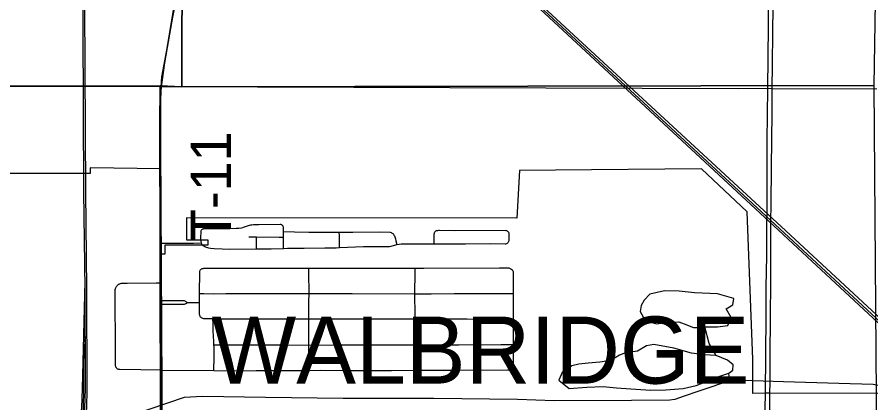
# Model space of a CAD drawing. Extents: x 0 to 40.2, y 0 to 22.
# Drawn here: x 4.538 to 5.744, y 15.808 to 16.354 of the extents above; entities that cross this region are included whole.
import ezdxf

# ---------------------------------------------------------------- set-up
doc = ezdxf.new("R2010")
doc.units = 0
for name, color, linetype in [('GM_X_Corporation', 7, 'Continuous'), ('GM_X_County_Road_Text', 7, 'Continuous'), ('GM_X_Major_River', 7, 'Continuous'), ('GM_X_Minor_Lake', 7, 'Continuous'), ('GM_X_Minor_Lake_Text', 7, 'Continuous'), ('GM_X_Rail_Line', 7, 'Continuous'), ('GM_X_Unincorporated', 7, 'Continuous'), ('GM_X_Unincorporated_Location', 7, 'Continuous'), ('GM_X_US_Location', 7, 'Continuous')]:
    doc.layers.add(name, color=color, linetype=linetype)

msp = doc.modelspace()

# ---------------------------------------------------------------- linework, layer by layer
at = {"layer": 'GM_X_Corporation'}
for points in [[(4.773, 17.2675), (4.7705, 16.2552), (4.7398, 16.2563), (3.7748, 16.2549), (3.7642, 17.2609)], [(4.773, 17.2675), (5.7644, 17.2596), (5.7484, 16.2569), (4.7705, 16.2552)], [(3.7748, 16.2549), (4.7398, 16.2563), (4.745, 15.3208), (3.7481, 15.3357), (3.7456, 16.2537)], [(5.7484, 16.2569), (5.7558, 15.3168), (4.745, 15.3208), (4.7398, 16.2563), (4.7705, 16.2552)]]:
    msp.add_lwpolyline(points, close=True, dxfattribs=at)
for points in [[(2.952, 16.2558), (3.7668, 16.256), (3.978, 16.2564), (4.3662, 15.7222), (4.3657, 15.832), (4.4899, 15.8293), (4.4389, 16.1327), (4.4182, 16.2558), (4.7417, 16.2555), (5.5568, 16.2525), (5.5984, 16.253), (5.6048, 16.2528), (5.7527, 16.2521)], [(5.7542, 15.8217), (5.6015, 15.8223), (5.5951, 15.8223), (5.5775, 15.8216), (5.5774, 15.8697), (5.5697, 16.0785), (5.5049, 16.1393), (5.3497, 16.1377), (5.2476, 16.1366), (5.2442, 16.0695), (4.777, 16.0697), (4.777, 16.039), (4.8072, 16.039), (4.8072, 16.0311), (4.7465, 16.0314), (4.7465, 16.0187), (4.741, 16.0186), (4.741, 16.0345), (4.7408, 16.1389), (4.6409, 16.1407), (4.641, 16.1323), (4.4389, 16.1327)]]:
    msp.add_lwpolyline(points, dxfattribs=at)
at = {"layer": 'GM_X_Major_River'}
for points in [[(4.1455, 17.415), (4.1542, 17.4069), (4.3224, 17.2484), (4.5126, 17.0764), (4.6277, 16.9694), (4.7733, 16.8366), (5.084, 16.5474), (5.609, 16.0605), (6.0377, 15.6628), (6.1678, 15.5423), (6.5654, 15.1729), (7.036, 14.7358), (7.4144, 14.3845), (7.7209, 14.1)], [(4.1471, 17.4167), (4.1558, 17.4086), (4.3239, 17.2501), (4.5142, 17.0781), (4.6293, 16.9711), (4.7748, 16.8383), (5.0856, 16.5491), (5.6113, 16.0632), (6.0399, 15.6663), (6.1698, 15.5443), (6.5669, 15.1758), (7.0383, 14.7375), (7.4155, 14.3872), (7.7237, 14.1)], [(4.595, 15.7016), (4.5966, 15.7037), (4.6105, 15.7227), (4.6181, 15.7396), (4.6243, 15.7572), (4.6309, 15.7811), (4.6337, 15.8009), (4.6346, 15.8282), (4.6339, 15.9696), (4.6323, 16.1067), (4.6306, 16.4569), (4.6254, 16.8469), (4.6254, 16.9694), (4.6218, 17.3067), (4.6212, 17.3587), (4.6206, 17.424)], [(4.5969, 15.7002), (4.5984, 15.7023), (4.6125, 15.7215), (4.6203, 15.7387), (4.6265, 15.7565), (4.6332, 15.7806), (4.6361, 15.8007), (4.637, 15.8282), (4.6362, 15.9697), (4.6347, 16.1067), (4.633, 16.4569), (4.6278, 16.847), (4.6277, 16.9694), (4.6241, 17.3067), (4.6236, 17.3587), (4.623, 17.424)], [(4.7243, 16.8813), (4.7752, 16.8317), (5.0824, 16.5458), (5.6074, 16.0588), (6.0352, 15.6606), (6.1639, 15.542), (6.5637, 15.1714), (7.0334, 14.7344), (7.4114, 14.3836), (7.7174, 14.1)], [(4.773, 16.8372), (4.7746, 16.4892), (4.7716, 16.4434), (4.7496, 16.309), (4.7417, 16.2693), (4.7392, 16.2247), (4.7399, 15.7814), (4.7434, 15.1836)], [(4.5912, 15.7043), (4.5928, 15.7065), (4.6065, 15.725), (4.6138, 15.7413), (4.6198, 15.7586), (4.6264, 15.7821), (4.6291, 15.8013), (4.63, 15.8283), (4.6338, 15.9798)], [(4.5931, 15.703), (4.5947, 15.7051), (4.6085, 15.7238), (4.6159, 15.7405), (4.622, 15.7579), (4.6286, 15.7816), (4.6314, 15.8011), (4.6323, 15.8282), (4.6321, 15.8675), (4.6343, 15.9023)]]:
    msp.add_lwpolyline(points, dxfattribs=at)
at = {"layer": 'GM_X_Minor_Lake'}
for points in [[(5.5258, 15.8755), (5.516, 15.8925), (5.5098, 15.9158)], [(5.5489, 15.8408), (5.6211, 15.8385), (5.699, 15.8364), (5.7478, 15.8349), (5.7802, 15.8283), (5.8134, 15.8228), (5.8409, 15.8225), (5.8804, 15.8707), (5.9029, 15.8722), (5.9152, 15.8724), (5.9231, 15.8681), (5.9338, 15.8524), (5.9479, 15.8355), (5.9601, 15.8315), (5.9759, 15.8354), (5.9938, 15.8408)], [(5.5489, 15.8408), (5.544, 15.8456), (5.5438, 15.8503)], [(5.5489, 15.8408), (5.4998, 15.8245), (5.4804, 15.818), (5.4675, 15.8132), (5.4603, 15.8122), (5.4062, 15.8116), (5.2968, 15.8114), (5.245, 15.813), (5.1266, 15.8146), (4.9988, 15.8147), (4.8887, 15.8158), (4.8002, 15.8172), (4.7741, 15.8161), (4.6767, 15.7828), (4.6101, 15.7576), (4.5602, 15.7399), (4.5188, 15.7284), (4.4621, 15.7046), (4.432, 15.6949), (4.4188, 15.6924), (4.4043, 15.6911), (4.3976, 15.6884)]]:
    msp.add_lwpolyline(points, dxfattribs=at)
at = {"layer": 'GM_X_Minor_Lake_Text'}
for p, q in [((5.5015, 15.9151), (5.5098, 15.9158)), ((5.4547, 15.827), (5.479, 15.8287))]:
    msp.add_line(p, q, dxfattribs=at)
for points in [[(5.5098, 15.9158), (5.5276, 15.916), (5.5424, 15.9175), (5.547, 15.9288), (5.5399, 15.9414), (5.5494, 15.947), (5.5509, 15.9557), (5.5275, 15.9623), (5.495, 15.9637), (5.4735, 15.9661), (5.4527, 15.9666), (5.4322, 15.9622), (5.4238, 15.9535), (5.4196, 15.9459), (5.4184, 15.9376), (5.4255, 15.925), (5.4414, 15.92), (5.4577, 15.9226), (5.4728, 15.9228), (5.4803, 15.9201), (5.4939, 15.9147), (5.5015, 15.9151)], [(5.479, 15.8287), (5.4975, 15.8328), (5.5157, 15.8402), (5.5279, 15.8451), (5.5438, 15.8503), (5.5491, 15.8548), (5.5499, 15.862), (5.5416, 15.8689), (5.5258, 15.8755), (5.5088, 15.8763), (5.491, 15.8787), (5.4661, 15.8857), (5.4378, 15.8908), (5.4272, 15.889), (5.4146, 15.8815), (5.3976, 15.8789), (5.3893, 15.876), (5.3767, 15.8681), (5.3612, 15.8659), (5.3446, 15.8645), (5.3317, 15.8631), (5.3218, 15.8609), (5.3082, 15.8515), (5.3036, 15.8405), (5.3182, 15.8286), (5.3428, 15.8304), (5.3659, 15.8314), (5.3848, 15.8297), (5.4052, 15.8281), (5.4332, 15.8264), (5.4547, 15.827)]]:
    msp.add_lwpolyline(points, dxfattribs=at)
at = {"layer": 'GM_X_Rail_Line'}
msp.add_line((4.7412, 16.018), (4.7413, 16.034), dxfattribs=at)
for points in [[(4.7419, 16.255), (4.7436, 16.268), (4.7467, 16.2889), (4.7536, 16.3294), (4.7579, 16.3533), (4.7638, 16.3851), (4.7681, 16.4109), (4.7706, 16.4273), (4.7736, 16.4484), (4.7745, 16.4578), (4.7752, 16.4634), (4.7757, 16.4688), (4.776, 16.4747), (4.7763, 16.482), (4.7767, 16.4988), (4.7767, 16.508)], [(4.7409, 16.1384), (4.741, 16.1539), (4.7407, 16.1732), (4.7407, 16.2), (4.7407, 16.223), (4.741, 16.2361), (4.7415, 16.2491), (4.7419, 16.255)], [(4.7413, 16.034), (4.741, 16.1012), (4.7411, 16.1139), (4.7409, 16.1374), (4.7409, 16.1384)], [(4.7413, 16.034), (4.7514, 16.034), (4.7675, 16.0341), (4.7779, 16.0341), (4.7872, 16.0342), (4.7977, 16.0344)], [(4.7416, 15.9778), (4.7415, 15.9952), (4.7412, 16.0151), (4.7412, 16.018)], [(4.7417, 15.9478), (4.7416, 15.953), (4.7416, 15.9559), (4.7416, 15.9721), (4.7416, 15.9778)], [(4.742, 15.9054), (4.7418, 15.9205), (4.7419, 15.9329), (4.7417, 15.9478)], [(4.7422, 15.8545), (4.7422, 15.8974), (4.742, 15.9054)], [(4.7417, 15.7843), (4.7417, 15.8139), (4.7422, 15.8545)]]:
    msp.add_lwpolyline(points, dxfattribs=at)
at = {"layer": 'GM_X_Unincorporated'}
for points in [[(5.605, 16.2523), (5.6055, 16.2864), (5.6059, 16.3318), (5.6062, 16.3679), (5.6068, 16.4412), (5.6077, 16.5109), (5.6092, 16.6091), (5.6095, 16.6701), (5.6096, 16.6826), (5.6096, 16.7167), (5.6102, 16.7509), (5.6104, 16.7643), (5.6109, 16.7907), (5.6114, 16.8342), (5.6113, 16.8517)], [(5.5926, 15.6316), (5.594, 15.6823), (5.5945, 15.7165), (5.5947, 15.7625), (5.595, 15.8004), (5.5953, 15.8217), (5.5962, 15.9315), (5.5964, 15.9719), (5.5971, 16.016), (5.5975, 16.0546), (5.5977, 16.0869), (5.5977, 16.1485), (5.5979, 16.1789), (5.5986, 16.2524), (5.5995, 16.3412), (5.6, 16.3965)], [(5.6017, 15.8217), (5.6018, 15.8379), (5.6022, 15.8714), (5.6026, 15.9324), (5.6031, 15.9765), (5.6032, 16.0144), (5.6031, 16.0636), (5.6034, 16.0903), (5.6041, 16.1407), (5.6045, 16.1805), (5.6048, 16.2178), (5.605, 16.2523)], [(5.6017, 15.573), (5.6013, 15.6309), (5.601, 15.6701), (5.601, 15.7211), (5.6017, 15.8217)]]:
    msp.add_lwpolyline(points, dxfattribs=at)
at = {"layer": 'GM_X_Unincorporated_Location'}
for p, q in [((4.9144, 16.0425), (4.9144, 16.0504)), ((4.8655, 16.043), (4.8762, 16.0428)), ((4.7954, 15.9502), (4.7955, 15.9628)), ((4.9502, 15.8901), (4.9501, 15.927)), ((4.7422, 15.8545), (4.8159, 15.8542))]:
    msp.add_line(p, q, dxfattribs=at)
for points in [[(4.9144, 16.0504), (4.9144, 16.0558), (4.9143, 16.0567), (4.9139, 16.0575), (4.9136, 16.0582), (4.9131, 16.0588), (4.9126, 16.0594), (4.9119, 16.0599), (4.9113, 16.0602), (4.9104, 16.0604), (4.9095, 16.0605), (4.8795, 16.0599), (4.8719, 16.06), (4.8695, 16.0597), (4.8675, 16.0594), (4.8657, 16.0589), (4.8603, 16.057), (4.8574, 16.0561), (4.8549, 16.0555), (4.8511, 16.0549), (4.8472, 16.0546), (4.8386, 16.0542), (4.8169, 16.0542), (4.8014, 16.0541), (4.8007, 16.054), (4.7999, 16.0538), (4.7991, 16.0533), (4.7985, 16.0528), (4.7981, 16.0521), (4.7976, 16.0514), (4.7974, 16.0507), (4.7973, 16.0498), (4.7972, 16.0421), (4.7973, 16.0362), (4.7977, 16.0344)], [(4.9144, 16.0504), (4.9297, 16.0501), (4.9501, 16.0497), (4.9793, 16.0495), (4.9931, 16.0495)], [(4.9931, 16.0495), (5.0122, 16.0498), (5.0506, 16.0499), (5.065, 16.0494), (5.0662, 16.0492), (5.0671, 16.0489), (5.0679, 16.0484), (5.0687, 16.0477), (5.0696, 16.0468), (5.0704, 16.0456), (5.071, 16.0446), (5.0717, 16.0428), (5.0725, 16.04), (5.0732, 16.0372), (5.0744, 16.0322)], [(4.9933, 16.0278), (4.9932, 16.0384), (4.9932, 16.0445), (4.9931, 16.0495)], [(5.1265, 16.0331), (5.1295, 16.0331), (5.1516, 16.0331), (5.1717, 16.0333), (5.2067, 16.0334), (5.2276, 16.0329), (5.2286, 16.0331), (5.2297, 16.0335), (5.2306, 16.034), (5.2314, 16.0347), (5.232, 16.0354), (5.2324, 16.0361), (5.2328, 16.0368), (5.2331, 16.0379), (5.2334, 16.0401), (5.2332, 16.0467), (5.233, 16.0483), (5.2327, 16.049), (5.2321, 16.0498), (5.2315, 16.0504), (5.2307, 16.0509), (5.2298, 16.0514), (5.2288, 16.0516), (5.2276, 16.0518), (5.1555, 16.0515), (5.1347, 16.0519), (5.1334, 16.0518), (5.132, 16.0517), (5.1309, 16.0516), (5.1301, 16.0513), (5.1292, 16.0509), (5.1286, 16.0504), (5.1281, 16.0499), (5.1277, 16.0492), (5.1273, 16.0485), (5.127, 16.0477), (5.1268, 16.0465), (5.1267, 16.0413), (5.1265, 16.0331)], [(4.876, 16.0261), (4.876, 16.0306), (4.8762, 16.0378), (4.8762, 16.0428)], [(4.8762, 16.0428), (4.9083, 16.0426), (4.9144, 16.0425)], [(4.9144, 16.0267), (4.9144, 16.0319), (4.9144, 16.0425)], [(4.7977, 16.0344), (4.7983, 16.0331), (4.7989, 16.0322), (4.7995, 16.0316), (4.8005, 16.0308), (4.8015, 16.0302), (4.803, 16.0294), (4.8051, 16.0285), (4.8067, 16.028), (4.8083, 16.0276), (4.8111, 16.0271), (4.8161, 16.0266), (4.8274, 16.026), (4.8379, 16.0258), (4.876, 16.0261)], [(4.876, 16.0261), (4.8969, 16.026), (4.9144, 16.0267)], [(4.9144, 16.0267), (4.9199, 16.0269), (4.9435, 16.0272), (4.9727, 16.0273), (4.9889, 16.0277), (4.9933, 16.0278)], [(4.9933, 16.0278), (5.0274, 16.0293), (5.0541, 16.0296), (5.0643, 16.0295), (5.0662, 16.0297), (5.068, 16.0301), (5.0728, 16.0318), (5.0744, 16.0322)], [(5.0744, 16.0322), (5.0778, 16.0327), (5.0805, 16.0329), (5.1045, 16.0332), (5.1265, 16.0331)], [(4.7955, 15.9628), (4.7958, 15.9938), (4.7959, 15.9944), (4.7962, 15.9951), (4.7965, 15.9958), (4.7969, 15.9963), (4.7974, 15.9969), (4.798, 15.9974), (4.7986, 15.9978), (4.7993, 15.9981), (4.7999, 15.9983), (4.8008, 15.9985), (4.8016, 15.9987), (4.8023, 15.9987), (4.828, 15.9987), (4.846, 15.9986), (4.9207, 15.9986), (4.9374, 15.9986), (4.9501, 15.9986)], [(4.9501, 15.9986), (5.0251, 15.9986), (5.0717, 15.9987), (5.1004, 15.9988)], [(4.9504, 15.9629), (4.9501, 15.9923), (4.9501, 15.9986)], [(5.1001, 15.9626), (5.1003, 15.9931), (5.1004, 15.9988)], [(5.1004, 15.9988), (5.1127, 15.9989), (5.2196, 15.9993), (5.23, 15.9994), (5.2307, 15.9993), (5.2314, 15.9992), (5.2326, 15.999), (5.2337, 15.9987), (5.2344, 15.9984), (5.2352, 15.998), (5.236, 15.9975)], [(5.2394, 15.9629), (5.2393, 15.9728), (5.2392, 15.9926), (5.2391, 15.9934), (5.2387, 15.9946), (5.2381, 15.9955), (5.2377, 15.996), (5.2365, 15.997), (5.236, 15.9975)], [(4.7422, 15.8545), (4.683, 15.8557), (4.6817, 15.8557), (4.6807, 15.8559), (4.6797, 15.8562), (4.679, 15.8566), (4.6785, 15.8571), (4.6781, 15.8577), (4.6777, 15.8583), (4.6774, 15.8589), (4.6772, 15.8596), (4.6769, 15.8608), (4.6769, 15.8623), (4.6768, 15.8802), (4.6764, 15.9647), (4.6765, 15.9671), (4.6766, 15.9687), (4.6769, 15.9698), (4.6772, 15.9708), (4.6776, 15.9718), (4.6781, 15.9727), (4.6787, 15.9735), (4.6794, 15.9744), (4.6802, 15.9752), (4.6811, 15.9759), (4.682, 15.9764), (4.6828, 15.9768), (4.6839, 15.9771), (4.6853, 15.9775), (4.6867, 15.9776), (4.6932, 15.9777), (4.7342, 15.9778), (4.7416, 15.9778)], [(4.7416, 15.953), (4.7492, 15.9531), (4.756, 15.9531), (4.772, 15.9531), (4.773, 15.953), (4.7738, 15.9529), (4.7748, 15.9527), (4.7754, 15.9523), (4.7788, 15.9503)], [(4.7955, 15.9628), (4.8016, 15.9628), (4.8158, 15.9626), (4.8326, 15.9628), (4.8842, 15.9628), (4.9309, 15.9629), (4.9504, 15.9629)], [(4.9501, 15.927), (4.9503, 15.9514), (4.9504, 15.9629)], [(4.9504, 15.9629), (4.9638, 15.9628), (5.0111, 15.9628), (5.1001, 15.9626)], [(5.1001, 15.9626), (5.123, 15.9625), (5.1553, 15.9628), (5.1914, 15.9629), (5.2325, 15.9629), (5.2394, 15.9629)], [(5.1005, 15.927), (5.1005, 15.9324), (5.1001, 15.9626)], [(5.2394, 15.9269), (5.2395, 15.9455), (5.2395, 15.9548), (5.2394, 15.9629)], [(4.7417, 15.9478), (4.7472, 15.9478), (4.7722, 15.9478), (4.7733, 15.9479), (4.7742, 15.9481), (4.7752, 15.9484), (4.7762, 15.9489), (4.7788, 15.9503)], [(4.7788, 15.9503), (4.7889, 15.9503), (4.7954, 15.9502)], [(4.8143, 15.9271), (4.8032, 15.9272), (4.8019, 15.9273), (4.8009, 15.9275), (4.8001, 15.9278), (4.7991, 15.9282), (4.7983, 15.9287), (4.7978, 15.9292), (4.7971, 15.9297), (4.7966, 15.9304), (4.7963, 15.9309), (4.7959, 15.9317), (4.7958, 15.9324), (4.7956, 15.9333), (4.7955, 15.9344), (4.7954, 15.9502)], [(4.8143, 15.9271), (4.8248, 15.9271), (4.8515, 15.927), (4.8951, 15.927), (4.9243, 15.927), (4.9501, 15.927)], [(4.816, 15.8903), (4.8159, 15.895), (4.8151, 15.9101), (4.8147, 15.921), (4.8143, 15.9271)], [(4.9501, 15.927), (4.9616, 15.927), (5.0468, 15.9271), (5.1005, 15.927)], [(5.1005, 15.927), (5.145, 15.927), (5.1736, 15.927), (5.2309, 15.9269), (5.2394, 15.9269)], [(5.1005, 15.8903), (5.1005, 15.9154), (5.1005, 15.927)], [(5.2394, 15.891), (5.2395, 15.8957), (5.2394, 15.9175), (5.2394, 15.9269)], [(4.8159, 15.8542), (4.816, 15.8589), (4.8162, 15.8686), (4.8161, 15.8776), (4.8161, 15.8869), (4.816, 15.8903)], [(4.816, 15.8903), (4.8258, 15.8903), (4.8562, 15.8906), (4.9165, 15.8904), (4.9502, 15.8901)], [(4.9502, 15.8901), (4.9957, 15.8903), (5.0369, 15.8903), (5.0849, 15.8903), (5.1005, 15.8903)], [(4.9504, 15.8543), (4.9503, 15.8638), (4.9502, 15.8812), (4.9502, 15.8901)], [(5.1005, 15.8544), (5.1004, 15.8622), (5.1003, 15.877), (5.1005, 15.8903)], [(5.1005, 15.8903), (5.1224, 15.8904), (5.1619, 15.8906), (5.2215, 15.8907), (5.2394, 15.891)], [(5.1005, 15.8544), (5.1172, 15.8545), (5.1613, 15.8544), (5.2309, 15.8549), (5.2328, 15.8549), (5.2342, 15.8551), (5.2352, 15.8553), (5.236, 15.8556), (5.2366, 15.8559), (5.2375, 15.8566), (5.238, 15.857), (5.2384, 15.8575), (5.239, 15.8585), (5.2393, 15.8596), (5.2394, 15.8789), (5.2394, 15.891)], [(4.8159, 15.8542), (4.8366, 15.8538), (4.8758, 15.8539), (4.9106, 15.854), (4.9504, 15.8543)], [(4.9504, 15.8543), (4.966, 15.8545), (5.0104, 15.8543), (5.0668, 15.8543), (5.1005, 15.8544)]]:
    msp.add_lwpolyline(points, dxfattribs=at)

# ---------------------------------------------------------------- texts
at = {"layer": 'GM_X_County_Road_Text'}
msp.add_text('T-11', height=0.05682, rotation=90.0081, dxfattribs=at).set_placement((4.8401, 16.0357))
at = {"layer": 'GM_X_US_Location'}
msp.add_text('WALBRIDGE', height=0.0947, rotation=0, dxfattribs=at).set_placement((4.8127, 15.8356))

doc.saveas('drawing.dxf')
